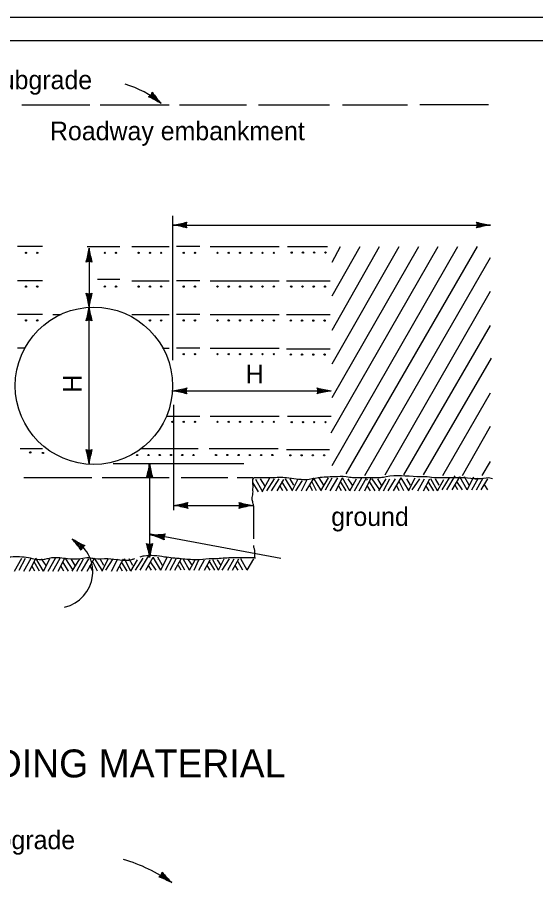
# Model space of a CAD drawing. Extents: x 0 to 390, y 0 to 265.
# Drawn here: x 206.6 to 262.2, y 172.1 to 265 of the extents above; entities that cross this region are included whole.
import ezdxf

# ---------------------------------------------------------------- set-up
doc = ezdxf.new("R2010")
doc.units = 0
doc.layers.add('D_Details', color=7, linetype='Continuous')
doc.layers.add('Default', color=7, linetype='Continuous')

msp = doc.modelspace()

# ---------------------------------------------------------------- linework, layer by layer
at = {"layer": 'D_Details'}
for p, q in [((207.054, 255.601), (214.354, 255.601)), ((215.454, 255.601), (222.854, 255.601)), ((223.954, 255.601), (231.154, 255.601)), ((232.454, 255.601), (240.054, 255.601)), ((241.454, 255.601), (248.454, 255.601)), ((257.154, 255.601), (249.754, 255.601)), ((223.254, 228.201), (223.254, 243.701)), ((223.254, 242.701), (257.354, 242.701)), ((209.254, 240.401), (206.554, 240.401)), ((214.054, 240.401), (217.554, 240.401)), ((214.254, 240.201), (214.254, 233.901)), ((218.854, 240.401), (222.854, 240.401)), ((226.154, 240.401), (223.654, 240.401)), ((227.254, 240.401), (234.654, 240.401)), ((235.554, 240.401), (239.854, 240.401)), ((240.254, 220.401), (251.754, 240.401)), ((240.354, 231.401), (245.454, 240.401)), ((240.354, 235.101), (243.354, 240.401)), ((240.354, 238.701), (241.254, 240.401)), ((240.354, 224.201), (249.654, 240.401)), ((240.354, 227.801), (247.554, 240.401)), ((240.354, 216.901), (253.854, 240.401)), ((241.854, 216.001), (255.954, 240.401)), ((243.854, 215.801), (257.354, 239.201)), ((215.154, 236.901), (217.554, 236.901)), ((209.254, 236.701), (206.554, 236.701)), ((218.854, 236.701), (222.854, 236.701)), ((226.154, 236.701), (223.654, 236.701)), ((227.254, 236.701), (234.654, 236.701)), ((235.454, 236.701), (240.154, 236.701)), ((246.054, 215.901), (257.354, 235.601)), ((214.254, 217.101), (214.254, 233.901)), ((209.254, 233.101), (206.554, 233.101)), ((210.354, 233.101), (211.254, 233.101)), ((218.854, 233.101), (222.854, 233.101)), ((226.154, 233.101), (223.654, 233.101)), ((227.254, 233.101), (234.654, 233.101)), ((235.454, 233.101), (240.154, 233.101)), ((248.054, 215.901), (257.354, 231.901)), ((207.354, 229.501), (206.554, 229.501)), ((222.154, 229.501), (222.854, 229.501)), ((226.154, 229.501), (223.654, 229.501)), ((227.254, 229.501), (234.654, 229.501)), ((235.454, 229.401), (240.154, 229.401)), ((250.154, 215.901), (257.454, 228.401)), ((223.254, 224.901), (240.254, 224.901)), ((252.254, 215.801), (257.354, 224.701)), ((223.354, 212.101), (223.354, 223.401)), ((222.554, 222.201), (226.154, 222.201)), ((227.254, 222.201), (234.654, 222.201)), ((235.554, 222.201), (240.254, 222.201)), ((254.354, 215.801), (257.354, 221.101)), ((206.854, 218.701), (209.254, 218.701)), ((219.854, 218.701), (225.954, 218.701)), ((227.154, 218.701), (234.554, 218.701)), ((235.454, 218.601), (240.054, 218.601)), ((216.854, 217.101), (230.854, 217.101)), ((220.754, 217.101), (220.754, 213.001)), ((256.454, 215.801), (257.354, 217.301)), ((207.254, 215.601), (214.554, 215.601)), ((215.654, 215.601), (222.854, 215.601)), ((224.154, 215.601), (229.154, 215.601)), ((230.154, 215.601), (231.854, 215.601)), ((231.954, 215.601), (231.954, 215.601)), ((232.856, 214.072), (233.656, 215.572)), ((239.156, 214.272), (238.356, 215.572)), ((239.456, 214.772), (238.956, 215.572)), ((239.156, 214.172), (239.956, 215.572)), ((239.656, 214.272), (240.356, 215.572)), ((240.156, 214.172), (240.956, 215.572)), ((240.454, 215.701), (240.454, 215.701)), ((240.756, 214.172), (241.456, 215.572)), ((242.256, 214.172), (241.456, 215.572)), ((242.756, 214.172), (243.556, 215.572)), ((243.256, 214.172), (244.056, 215.572)), ((243.856, 214.172), (244.556, 215.572)), ((246.956, 214.172), (247.756, 215.572)), ((248.556, 214.272), (247.756, 215.572)), ((248.556, 214.172), (249.256, 215.572)), ((249.454, 215.701), (249.454, 215.701)), ((252.156, 214.272), (252.956, 215.572)), ((252.656, 214.272), (253.556, 215.772)), ((253.256, 214.272), (254.056, 215.672)), ((254.856, 214.272), (254.056, 215.672)), ((255.056, 214.772), (254.556, 215.672)), ((254.856, 214.272), (255.556, 215.672)), ((255.356, 214.272), (256.056, 215.572)), ((255.856, 214.272), (256.556, 215.572)), ((232.456, 214.072), (231.856, 215.072)), ((232.856, 214.172), (232.156, 215.372)), ((232.354, 215.401), (232.354, 215.401)), ((233.156, 214.672), (232.656, 215.472)), ((233.356, 214.172), (234.156, 215.472)), ((233.856, 214.172), (234.656, 215.472)), ((234.456, 214.172), (235.156, 215.372)), ((235.056, 214.172), (234.756, 214.672)), ((235.556, 214.172), (234.956, 215.172)), ((236.056, 214.272), (235.356, 215.472)), ((236.256, 214.772), (235.856, 215.472)), ((236.056, 214.172), (236.656, 215.372)), ((236.456, 214.172), (237.156, 215.272)), ((237.056, 214.172), (237.656, 215.372)), ((237.556, 214.172), (238.356, 215.472)), ((238.256, 214.172), (237.956, 214.772)), ((238.656, 214.172), (238.156, 215.172)), ((241.356, 214.172), (241.056, 214.672)), ((241.856, 214.172), (241.256, 215.172)), ((242.556, 214.772), (242.056, 215.472)), ((242.256, 214.172), (242.956, 215.472)), ((243.954, 215.501), (243.954, 215.501)), ((244.154, 215.401), (244.054, 215.301)), ((244.456, 214.172), (244.156, 214.672)), ((244.956, 214.172), (244.356, 215.172)), ((245.456, 214.272), (244.656, 215.472)), ((245.656, 214.772), (245.256, 215.472)), ((245.356, 214.172), (246.156, 215.472)), ((245.856, 214.172), (246.556, 215.472)), ((246.356, 214.172), (247.156, 215.472)), ((247.556, 214.172), (247.256, 214.772)), ((248.056, 214.172), (247.556, 215.172)), ((248.756, 214.772), (248.356, 215.472)), ((248.956, 214.272), (249.756, 215.472)), ((249.556, 214.172), (250.256, 215.472)), ((250.156, 214.172), (250.856, 215.472)), ((250.756, 214.172), (250.456, 214.672)), ((251.256, 214.172), (250.656, 215.172)), ((251.656, 214.172), (250.956, 215.472)), ((251.856, 214.772), (251.456, 215.472)), ((251.656, 214.172), (252.356, 215.372)), ((253.856, 214.272), (253.556, 214.772)), ((254.356, 214.272), (253.756, 215.172)), ((255.854, 215.501), (255.754, 215.401)), ((255.854, 215.401), (255.854, 215.401)), ((256.356, 214.272), (257.056, 215.472)), ((257.056, 214.272), (256.756, 214.772)), ((220.754, 213.001), (220.754, 207.001)), ((223.354, 212.601), (231.854, 212.601)), ((234.854, 206.901), (220.854, 209.501)), ((206.247, 205.554), (207.047, 206.954)), ((206.747, 205.654), (207.447, 206.954)), ((207.247, 205.554), (208.047, 206.954)), ((207.847, 205.554), (208.547, 206.954)), ((208.947, 205.554), (208.347, 206.554)), ((209.347, 205.554), (208.547, 206.954)), ((209.647, 206.154), (209.147, 206.854)), ((209.347, 205.554), (210.047, 206.854)), ((209.454, 206.901), (209.454, 206.901)), ((209.754, 206.801), (209.754, 206.801)), ((209.847, 205.554), (210.647, 206.954)), ((209.854, 206.801), (209.854, 206.801)), ((210.347, 205.554), (211.147, 206.954)), ((210.947, 205.554), (211.647, 206.954)), ((212.047, 205.554), (211.447, 206.554)), ((212.547, 205.654), (211.747, 206.854)), ((212.747, 206.154), (212.347, 206.854)), ((212.447, 205.554), (213.247, 206.854)), ((212.947, 205.554), (213.647, 206.854)), ((213.447, 205.554), (214.247, 206.854)), ((214.047, 205.554), (214.847, 206.954)), ((215.147, 205.554), (214.647, 206.554)), ((215.647, 205.654), (214.847, 206.954)), ((215.847, 206.154), (215.447, 206.854)), ((215.647, 205.554), (216.347, 206.954)), ((216.047, 205.654), (216.847, 206.854)), ((216.647, 205.554), (217.347, 206.854)), ((217.247, 205.554), (217.947, 206.854)), ((218.347, 205.554), (217.747, 206.554)), ((218.747, 205.554), (218.047, 206.854)), ((218.947, 206.154), (218.547, 206.854)), ((218.747, 205.554), (219.447, 206.754)), ((219.247, 205.654), (220.047, 206.954)), ((219.747, 205.654), (220.647, 207.154)), ((220.347, 205.654), (221.147, 207.054)), ((221.447, 205.654), (220.847, 206.554)), ((221.947, 205.654), (221.147, 207.054)), ((221.554, 206.801), (221.554, 206.801)), ((222.147, 206.154), (221.647, 207.054)), ((221.654, 206.801), (221.654, 206.801)), ((221.947, 205.654), (222.647, 207.054)), ((222.447, 205.654), (223.147, 206.954)), ((222.947, 205.654), (223.647, 206.954)), ((223.447, 205.654), (224.147, 206.854)), ((224.547, 205.654), (224.047, 206.554)), ((225.047, 205.654), (224.347, 206.854)), ((225.347, 206.154), (224.947, 206.754)), ((225.047, 205.654), (225.647, 206.754)), ((225.547, 205.654), (226.047, 206.754)), ((226.047, 205.654), (226.647, 206.754)), ((226.647, 205.654), (227.247, 206.754)), ((227.747, 205.654), (227.147, 206.654)), ((228.147, 205.654), (227.547, 206.754)), ((228.447, 206.154), (228.047, 206.754)), ((228.147, 205.654), (228.747, 206.854)), ((228.254, 207.001), (228.254, 207.001)), ((228.547, 205.654), (229.347, 206.854)), ((229.147, 205.654), (229.847, 206.854)), ((229.647, 205.654), (230.347, 206.854)), ((230.747, 205.654), (230.247, 206.554)), ((231.247, 205.654), (230.547, 206.854)), ((231.247, 205.654), (231.947, 206.854)), ((232.054, 207.001), (232.054, 206.901)), ((208.447, 205.554), (208.147, 206.054)), ((211.547, 205.554), (211.247, 206.054)), ((214.647, 205.554), (214.347, 206.154)), ((217.847, 205.554), (217.547, 206.054)), ((220.947, 205.654), (220.647, 206.154)), ((224.147, 205.654), (223.847, 206.154)), ((227.247, 205.654), (226.947, 206.154)), ((230.247, 205.654), (229.947, 206.154))]:
    msp.add_line(p, q, dxfattribs=at)
msp.add_lwpolyline([(249.454, 215.701), (250.554, 215.701), (251.254, 215.601), (252.354, 215.601), (253.054, 215.601), (253.954, 215.601), (254.554, 215.601), (255.554, 215.501), (256.354, 215.501), (257.154, 215.601), (257.554, 215.501)], dxfattribs=at)
for centre, radius in [((207.482, 239.723), 0.0674), ((208.691, 239.723), 0.0674), ((215.948, 239.723), 0.0674), ((217.158, 239.723), 0.0674), ((219.577, 239.723), 0.0674), ((220.786, 239.723), 0.0674), ((221.996, 239.723), 0.0674), ((224.415, 239.723), 0.0674), ((225.624, 239.723), 0.0674), ((228.043, 239.723), 0.0674), ((229.253, 239.723), 0.0674), ((230.463, 239.723), 0.0674), ((231.672, 239.723), 0.0674), ((232.882, 239.723), 0.0674), ((234.091, 239.723), 0.0674), ((236.009, 239.74), 0.0674), ((237.218, 239.74), 0.0674), ((238.428, 239.74), 0.0674), ((239.637, 239.74), 0.0674), ((207.482, 236.094), 0.0674), ((208.691, 236.094), 0.0674), ((215.948, 236.094), 0.0674), ((217.158, 236.094), 0.0674), ((219.577, 236.094), 0.0674), ((220.786, 236.094), 0.0674), ((221.996, 236.094), 0.0674), ((224.415, 236.094), 0.0674), ((225.624, 236.094), 0.0674), ((228.043, 236.094), 0.0674), ((229.253, 236.094), 0.0674), ((230.463, 236.094), 0.0674), ((231.672, 236.094), 0.0674), ((232.882, 236.094), 0.0674), ((234.091, 236.094), 0.0674), ((235.961, 236.09), 0.0674), ((237.171, 236.09), 0.0674), ((238.38, 236.09), 0.0674), ((239.59, 236.09), 0.0674), ((214.775, 225.446), 8.447), ((207.482, 232.466), 0.0674), ((208.691, 232.466), 0.0674), ((220.786, 232.466), 0.0674), ((221.996, 232.466), 0.0674), ((224.415, 232.466), 0.0674), ((225.624, 232.466), 0.0674), ((228.043, 232.466), 0.0674), ((229.253, 232.466), 0.0674), ((230.463, 232.466), 0.0674), ((231.672, 232.466), 0.0674), ((232.882, 232.466), 0.0674), ((234.091, 232.466), 0.0674), ((235.914, 232.44), 0.0674), ((237.123, 232.44), 0.0674), ((238.333, 232.44), 0.0674), ((239.543, 232.44), 0.0674), ((224.415, 228.837), 0.0674), ((225.624, 228.837), 0.0674), ((228.043, 228.837), 0.0674), ((229.253, 228.837), 0.0674), ((230.463, 228.837), 0.0674), ((231.672, 228.837), 0.0674), ((232.882, 228.837), 0.0674), ((234.091, 228.837), 0.0674), ((235.914, 228.79), 0.0674), ((237.123, 228.79), 0.0674), ((238.333, 228.79), 0.0674), ((239.543, 228.79), 0.0674), ((223.205, 221.58), 0.0674), ((224.415, 221.58), 0.0674), ((225.624, 221.58), 0.0674), ((228.043, 221.58), 0.0674), ((229.253, 221.58), 0.0674), ((230.463, 221.58), 0.0674), ((231.672, 221.58), 0.0674), ((232.882, 221.58), 0.0674), ((234.091, 221.58), 0.0674), ((236.009, 221.537), 0.0674), ((237.218, 221.537), 0.0674), ((238.428, 221.537), 0.0674), ((239.637, 221.537), 0.0674), ((207.941, 218.295), 0.0674), ((209.303, 218.234), 0.0674), ((219.424, 218.012), 0.0674), ((220.633, 218.012), 0.0674), ((221.843, 218.012), 0.0674), ((223.052, 218.012), 0.0674), ((224.262, 218.012), 0.0674), ((225.471, 218.012), 0.0674), ((227.89, 218.012), 0.0674), ((229.1, 218.012), 0.0674), ((230.31, 218.012), 0.0674), ((231.519, 218.012), 0.0674), ((232.729, 218.012), 0.0674), ((233.938, 218.012), 0.0674), ((235.867, 217.981), 0.0674), ((237.076, 217.981), 0.0674), ((238.286, 217.981), 0.0674), ((239.495, 217.981), 0.0674)]:
    msp.add_circle(centre, radius, dxfattribs=at)
for centre, radius, start, end in [((215.235, 247.801), 10.421, 49.64729, 73.91725), ((220.364, 257.117), 0.699, 292.8623, 346.43229), ((215.962, 246.238), 11.25, 57.64729, 65.45898), ((215.962, 246.238), 11.35, 60.64829, 65.07737), ((215.962, 246.238), 11.45, 63.00666, 64.81822), ((230.389, 263.218), 11.45, 214.47638, 216.28793), ((230.389, 263.218), 11.35, 214.21722, 218.6463), ((230.389, 263.218), 11.25, 213.83383, 221.64729), ((221.688, 253.841), 11.25, 278, 285.81169), ((221.688, 231.56), 11.25, 74.18653, 82), ((221.688, 253.841), 11.35, 281.00099, 285.43008), ((221.688, 231.56), 11.35, 74.56992, 78.99901), ((221.688, 253.841), 11.45, 283.35937, 285.17092), ((221.688, 231.56), 11.45, 74.82908, 76.64064), ((225.378, 242.701), 0.699, 153.215, 206.78499), ((258.919, 253.841), 11.25, 254.18653, 262), ((255.23, 242.701), 0.699, 333.215, 26.78499), ((258.919, 231.56), 11.25, 98, 105.81169), ((258.919, 253.841), 11.35, 254.56992, 258.99901), ((258.919, 231.56), 11.35, 101.00099, 105.43008), ((258.919, 253.841), 11.45, 254.82908, 256.64064), ((258.919, 231.56), 11.45, 103.35937, 105.17092), ((203.113, 241.767), 11.25, 344.18653, 352), ((225.394, 241.767), 11.25, 188, 195.81169), ((214.254, 238.077), 0.699, 63.215, 116.78499), ((203.113, 241.767), 11.35, 344.56992, 348.99901), ((203.113, 241.767), 11.45, 344.82908, 346.64064), ((225.394, 241.767), 11.35, 191.00099, 195.43008), ((225.394, 241.767), 11.45, 193.35937, 195.17092), ((203.113, 232.335), 11.25, 8, 15.81169), ((214.254, 236.025), 0.699, 243.215, 296.78499), ((203.113, 232.335), 11.35, 11.00099, 15.43008), ((203.113, 232.335), 11.45, 13.35937, 15.17092), ((225.394, 232.335), 11.35, 164.56992, 168.99901), ((225.394, 232.335), 11.25, 164.18653, 172), ((225.394, 232.335), 11.45, 164.82908, 166.64064), ((203.113, 235.467), 11.25, 344.18653, 352), ((203.113, 235.467), 11.35, 344.56992, 348.99901), ((225.394, 235.467), 11.35, 191.00099, 195.43008), ((225.394, 235.467), 11.25, 188, 195.81169), ((214.254, 231.777), 0.699, 63.215, 116.78499), ((203.113, 235.467), 11.45, 344.82908, 346.64064), ((225.394, 235.467), 11.45, 193.35937, 195.17092), ((221.688, 236.041), 11.25, 278, 285.81169), ((221.688, 213.76), 11.25, 74.18653, 82), ((221.688, 236.041), 11.35, 281.00099, 285.43008), ((221.688, 213.76), 11.35, 74.56992, 78.99901), ((221.688, 236.041), 11.45, 283.35937, 285.17092), ((221.688, 213.76), 11.45, 74.82908, 76.64064), ((225.378, 224.901), 0.699, 153.215, 206.78499), ((241.819, 236.041), 11.25, 254.18653, 262), ((238.13, 224.901), 0.699, 333.215, 26.78499), ((241.819, 213.76), 11.25, 98, 105.81169), ((241.819, 236.041), 11.35, 254.56992, 258.99901), ((241.819, 213.76), 11.35, 101.00099, 105.43008), ((241.819, 236.041), 11.45, 254.82908, 256.64064), ((241.819, 213.76), 11.45, 103.35937, 105.17092), ((203.113, 215.535), 11.25, 8, 15.81169), ((214.254, 219.225), 0.699, 243.215, 296.78499), ((203.113, 215.535), 11.35, 11.00099, 15.43008), ((203.113, 215.535), 11.45, 13.35937, 15.17092), ((225.394, 215.535), 11.35, 164.56992, 168.99901), ((225.394, 215.535), 11.25, 164.18653, 172), ((225.394, 215.535), 11.45, 164.82908, 166.64064), ((209.613, 218.667), 11.25, 344.18653, 352), ((209.613, 218.667), 11.35, 344.56992, 348.99901), ((231.894, 218.667), 11.35, 191.00099, 195.43008), ((231.894, 218.667), 11.25, 188, 195.81169), ((220.754, 214.977), 0.699, 63.215, 116.78499), ((209.613, 218.667), 11.45, 344.82908, 346.64064), ((231.894, 218.667), 11.45, 193.35937, 195.17092), ((221.788, 223.741), 11.25, 278, 285.81169), ((221.788, 223.741), 11.35, 281.00099, 285.43008), ((225.478, 212.601), 0.699, 153.215, 206.78499), ((233.419, 223.741), 11.25, 254.18653, 262), ((229.73, 212.601), 0.699, 333.215, 26.78499), ((233.419, 223.741), 11.35, 254.56992, 258.99901), ((221.788, 201.46), 11.25, 74.18653, 82), ((221.788, 201.46), 11.35, 74.56992, 78.99901), ((221.788, 223.741), 11.45, 283.35937, 285.17092), ((221.788, 201.46), 11.45, 74.82908, 76.64064), ((233.419, 201.46), 11.25, 98, 105.81169), ((233.419, 201.46), 11.35, 101.00099, 105.43008), ((233.419, 223.741), 11.45, 254.82908, 256.64064), ((233.419, 201.46), 11.45, 103.35937, 105.17092), ((220.999, 220.697), 11.25, 269.46923, 277.28092), ((217.693, 198.662), 11.25, 65.65576, 73.46923), ((220.999, 220.697), 11.35, 272.47023, 276.89931), ((217.693, 198.662), 11.35, 66.03916, 70.46824), ((220.999, 220.697), 11.45, 274.8286, 276.64016), ((217.693, 198.662), 11.45, 66.29831, 68.10987), ((222.995, 209.132), 0.699, 144.68424, 198.25423), ((210.774, 205.473), 3.878, 282.80234, 64.51832), ((204.279, 201.23), 11.25, 35.71023, 43.5237), ((218.143, 218.673), 11.25, 239.5237, 247.33539), ((218.143, 218.673), 11.35, 242.5247, 246.95378), ((204.279, 201.23), 11.35, 36.09363, 40.52271), ((218.143, 218.673), 11.45, 244.88307, 246.69463), ((204.279, 201.23), 11.45, 36.35278, 38.16434), ((214.1, 207.655), 0.699, 114.73871, 168.3087), ((209.613, 205.435), 11.25, 8, 15.81169), ((220.754, 209.125), 0.699, 243.215, 296.78499), ((209.613, 205.435), 11.35, 11.00099, 15.43008), ((209.613, 205.435), 11.45, 13.35937, 15.17092), ((231.894, 205.435), 11.35, 164.56992, 168.99901), ((231.894, 205.435), 11.25, 164.18653, 172), ((231.894, 205.435), 11.45, 164.82908, 166.64064), ((213.241, 158.044), 17.198, 54.85646, 74.10434), ((221.403, 173.33), 0.699, 298.07147, 351.64146), ((221.403, 173.33), 0.699, 298.07147, 351.64146), ((218.008, 162.096), 11.45, 68.21583, 70.02739), ((218.008, 162.096), 11.45, 68.21583, 70.02739), ((230.833, 180.315), 11.45, 219.68554, 221.4971), ((230.833, 180.315), 11.45, 219.68554, 221.4971), ((230.833, 180.315), 11.35, 219.42639, 223.85547), ((230.833, 180.315), 11.35, 219.42639, 223.85547), ((230.833, 180.315), 11.25, 219.04299, 226.85646), ((230.833, 180.315), 11.25, 219.04299, 226.85646), ((218.008, 162.096), 11.25, 62.85646, 70.66815), ((218.008, 162.096), 11.25, 62.85646, 70.66815), ((218.008, 162.096), 11.35, 65.85746, 70.28654), ((218.008, 162.096), 11.35, 65.85746, 70.28654)]:
    msp.add_arc(centre, radius, start, end, dxfattribs=at)
for points in [[(231.954, 209.001), (231.954, 209.101), (231.954, 209.301), (231.954, 209.601), (231.954, 209.901), (231.954, 210.201), (231.954, 210.401), (231.954, 210.701), (231.954, 211.201), (231.954, 211.701), (231.954, 212.001), (231.954, 212.401), (231.854, 212.901), (231.754, 213.301), (231.854, 213.901), (231.854, 214.201), (231.854, 214.401), (231.854, 214.901), (231.854, 215.401), (231.954, 215.601)], [(231.954, 215.601), (233.854, 215.601), (235.454, 215.601), (237.554, 215.401), (238.854, 215.601), (240.554, 215.701)], [(240.554, 215.701), (241.854, 215.701), (242.554, 215.601), (243.654, 215.601), (244.254, 215.601), (244.854, 215.601), (245.554, 215.601), (246.154, 215.701), (249.454, 215.701)], [(232.054, 207.001), (232.054, 207.301), (232.054, 207.501), (232.054, 207.801), (231.954, 208.101), (231.954, 208.301)], [(198.054, 206.801), (198.354, 206.701), (199.854, 207.001), (201.354, 206.801), (202.654, 206.901), (203.754, 206.701), (204.754, 206.901), (205.854, 207.101), (207.754, 207.001), (209.254, 206.801), (210.254, 207.001), (211.954, 206.901), (213.354, 206.901), (214.254, 207.001), (214.854, 206.901), (216.254, 206.901), (218.854, 206.801), (219.154, 206.901)], [(219.754, 207.101), (220.154, 207.201), (222.354, 207.101), (224.154, 206.901), (225.754, 206.801), (227.154, 206.901)], [(227.154, 206.901), (227.654, 206.901), (229.254, 207.001), (231.054, 207.001), (232.054, 207.001)]]:
    msp.add_spline(points, degree=3, dxfattribs=at)
at = {"layer": 'Default'}
for points in [[(0, 265), (326.25, 265), (326.25, 255), (390, 255), (390, 37.5), (315, 37.5), (315, 0), (0, 0)], [(0, 262.5), (326.25, 262.5), (326.25, 252.5), (390, 252.5), (390, 40), (315, 40), (315, 2.5), (0, 2.5)]]:
    msp.add_lwpolyline(points, close=True, dxfattribs=at)

# ---------------------------------------------------------------- texts
at = {"layer": 'D_Details'}
for s, height, p in [('Finished subgrade', 2, (192.582, 257.286)), ('Roadway embankment', 2, (210.057, 251.802)), ('H', 2, (231.057, 225.702)), ('ground', 2, (240.257, 210.402)), ('ON UNYIELDING MATERIAL', 3, (182.508, 183.402)), ('Finished subgrade', 2, (190.757, 175.702))]:
    msp.add_text(s, height=height, dxfattribs=at).set_placement(p)
msp.add_text('H', height=2, rotation=90, dxfattribs=at).set_placement((213.457, 224.702))

doc.saveas('drawing.dxf')
